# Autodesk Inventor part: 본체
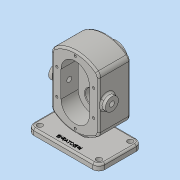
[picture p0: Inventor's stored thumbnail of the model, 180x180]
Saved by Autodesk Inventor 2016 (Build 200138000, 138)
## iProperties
Created: 2019-03
Part Number: 본체
Material: 일반
Document SubType Name: Modeling
Designer: Administrator
Density: 1 g/cm^3
Appearance: 기본값
Author: Administrator
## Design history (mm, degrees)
sketch "스케치1"
  geometry: L1 (-60, 36.5)-(60, 36.5); L2 (60, 36.5)-(60, -36.5); L3 (60, -36.5)-(-60, -36.5); L4 (-60, -36.5)-(-60, 36.5); L5 (-60, 36.5)-(60, -36.5); L6 (60, 36.5)-(-60, -36.5); 1 further point
  constraints: 12 end point, 2 midpoint, 2 parallel, 1 horizontal, 1 perpendicular
  dimensions: "d0" = 120 distance of L2.end L3.end; "d1" = 73 distance of L1.end L2.end
extrude "돌출1" new body sketch "스케치1" distance "d2" = 10; taper "d3" = 0 deg
node "작업 평면1"
sketch "스케치3"
  geometry: L1 (60, 0)-(60, -78); L2 (20, -78)-(100, -78); L3 (100, -78)-(100, -122.721); L4 (20, -122.721)-(20, -78); A1 r 60 centre (60, -78) between (20, -122.721) and (100, -122.721)
  constraints: 8 end point, 2 point on circle, 1 centre point, 1 coincident, 1 horizontal, 1 midpoint, 1 parallel, 1 perpendicular, 1 vertical
  dimensions: "d8" = 78 distance of L1.end L1.start; "d10" = 60 radius of A1; "d11" = 80 distance between parallel lines of L3 L4
extrude "돌출2" join sketch "스케치3" distance "d12" = 53; taper "d13" = 0 deg
node "작업 평면2"
sketch "스케치4"
  geometry: L1 (-60, 36.5)-(60, 36.5) reference; L2 (-6, 36.5)-(6, 36.5); L3 (6, 36.5)-(6, -6.5); L4 (6, -6.5)-(-6, -6.5); L5 (-6, -6.5)-(-6, 36.5); 2 further points
  constraints: 8 end point, 2 midpoint, 2 parallel, 1 horizontal, 1 perpendicular, 1 point on line
  dimensions: "d15" = 12 distance of L3.end L4.end; "d16" = 43 distance of L2.end L3.end
extrude "돌출3" join sketch "스케치4" stored distance "d17" = 53; taper "d18" = 0 deg
sketch "스케치5"
  geometry: L1 (100, -122.721)-(100, -33.279) reference; L2 (100, -78)-(20, -78); L3 (20, -122.721)-(20, -33.279) reference; C1 r 19 at (60, -100); 2 further points
  constraints: 3 midpoint, 2 end point, 1 centre point, 1 vertical alignment
  dimensions: "d19" = 38 diameter of C1; "d20" = 22 distance of point (60, -78) C1.centre
extrude "돌출4" join sketch "스케치5" distance "d21" = 17; taper "d22" = 0 deg
sketch "스케치6"
  geometry: L1 (60, 100)-(60, 56); L2 (36, 100)-(36, 56); L3 (84, 56)-(84, 100); C1 r 19 at (60, 100) reference; A1 r 24 centre (60, 100) between (84, 100) and (36, 100); A2 r 24 centre (60, 56) between (36, 56) and (84, 56); 2 further points
  constraints: 8 end point, 4 point on circle, 4 tangent, 2 centre point, 1 midpoint, 1 parallel, 1 vertical
  dimensions: "d23" = 44 distance of L1.start L1.end; "d25" = 24 radius of A2
extrude "돌출5" cut sketch "스케치6" distance "d26" = 29; taper "d27" = 0 deg
revolve "회전1" stored, may be unused: angle "d33" = 90 deg
hole "구멍1" diameter "d36" = 25; stored, may be unused: countersink angle "d40" = 90 deg, drill point angle "d42" = 0 deg; dims "d34" = 10, "d35" = 10, "d37" = 6, "d38" = 4, "d39" = 2, "d41" = 15
sketch "스케치8"
  geometry: L1 (89.443, 0)-(0, 0) reference; C1 r 11 at (44.721, 14); 3 further points
  constraints: 1 centre point, 1 coincident, 1 midpoint, 1 vertical alignment
  dimensions: "d43" = 14 distance from line of point (44.721, 14) L1; "d44" = 22 diameter of C1
extrude "돌출6" join sketch "스케치8" distance "d45" = 8; taper "d46" = 0 deg
hole "구멍2" diameter "d49" = 8.376; stored, may be unused: countersink angle "d53" = 90 deg, drill point angle "d55" = 0 deg; dims "d47" = 10, "d48" = 10, "d50" = 20, "d51" = 4, "d52" = 2, "d54" = 27.3
sketch "스케치9"
  geometry: L1 (60, -36.5)-(60, 36.5) reference; L2 (60, 36.5)-(6, 36.5) reference; 2 further points
  dimensions: "d56" = 10 distance from line of L1 point (50, 26.5); "d57" = 10 distance from line of point (50, 26.5) L2
hole "구멍3" sketch "스케치9" at (50, 26.5) diameter "d58" = 9; stored, may be unused: countersink angle "d62" = 90 deg, drill point angle "d64" = 0 deg; dims "d59" = 20, "d60" = 4, "d61" = 2, "d63" = 27.3
sketch "스케치10"
  geometry: L1 (60, 100)-(60, 131); L2 (60, 100)-(91, 100); C1 r 8.5 at (60, 100) reference; C2 r 19 at (60, 100) reference; 4 further points
  constraints: 4 end point, 2 coincident, 1 horizontal, 1 symmetric about line, 1 vertical
  dimensions: "d71" = 31 distance of L1.start L1.end; "d79" = 31 distance of L2.start L2.end
hole "구멍5" sketch "스케치10" at (60, 131), (91, 100), (29, 100) diameter "d80" = 4.134; stored, may be unused: countersink angle "d84" = 90 deg, drill point angle "d86" = 118 deg; dims "d81" = 10, "d82" = 4, "d83" = 2, "d85" = 12
chamfer "모따기1" distance "d87" = 1; stored, may be unused: second distance "d88" = 2, angle "d89" = 45 deg
fillet "모깎기1" dims "d93" = 0.5
fillet "모깎기2" dims "d94" = 10
fillet "모깎기5" dims "d97" = 3
fillet "모깎기6" dims "d98" = 3
sketch "스케치11"
  geometry: L1 (-50, -36.5)-(50, -36.5) reference; L2 (-60, 26.5)-(-60, -26.5) reference; 2 further points
  constraints: 1 other
  dimensions: "d99" = 10 distance from line of L1 point (0, -26.5); "d100" = 60 distance from line of L2 point (0, -26.5)
feature "엠보싱1" sketch "스케치11" dims "d0" = 120, "d1" = 73, "d101" = 0.5, "d102" = 0
node "솔리드1"
mirror "대칭1"
mirror "대칭2"
pattern_linear "직사각형 패턴1" dims "d67" = 53
mirror "대칭3"
sketch "스케치7"
  geometry: L1 (53.5, 81)-(53.5, 119) reference; L2 (-16.5, 100)-(12.5, 100) reference; L3 (53.5, 100)-(12.5, 100); L4 (12.5, 56)-(12.5, 100) reference; L5 (52.8, 114)-(46.2, 114); L6 (46.2, 114)-(46.2, 108.5); L7 (46.2, 108.5)-(27.5, 108.5); L8 (27.5, 108.5)-(27.5, 112.5); L9 (27.5, 112.5)-(12.5, 112.5); L10 (12.5, 100)-(12.5, 124) reference; L11 (12.5, 112.5)-(12.5, 100); L12 (53.5, 114.404)-(53.5, 100); L13 (52.8, 114)-(53.5, 114.404); 2 further points
  constraints: 18 end point, 5 perpendicular, 3 point on line, 2 collinear, 1 horizontal, 1 midpoint
  dimensions: "d28" = 25 diameter of L9 L3; "d29" = 17 diameter of L7 L3; "d30" = 28 diameter of L5 L3; "d31" = 15 distance between parallel lines of L8 L10; "d32" = 7.3 distance between parallel lines of L1 L6; "d106" = 30 deg angle of L5 L13; "d107" = 0.7 distance from line of L12 L5.start
other parameters: "d4" = -53, "d14" = 78
